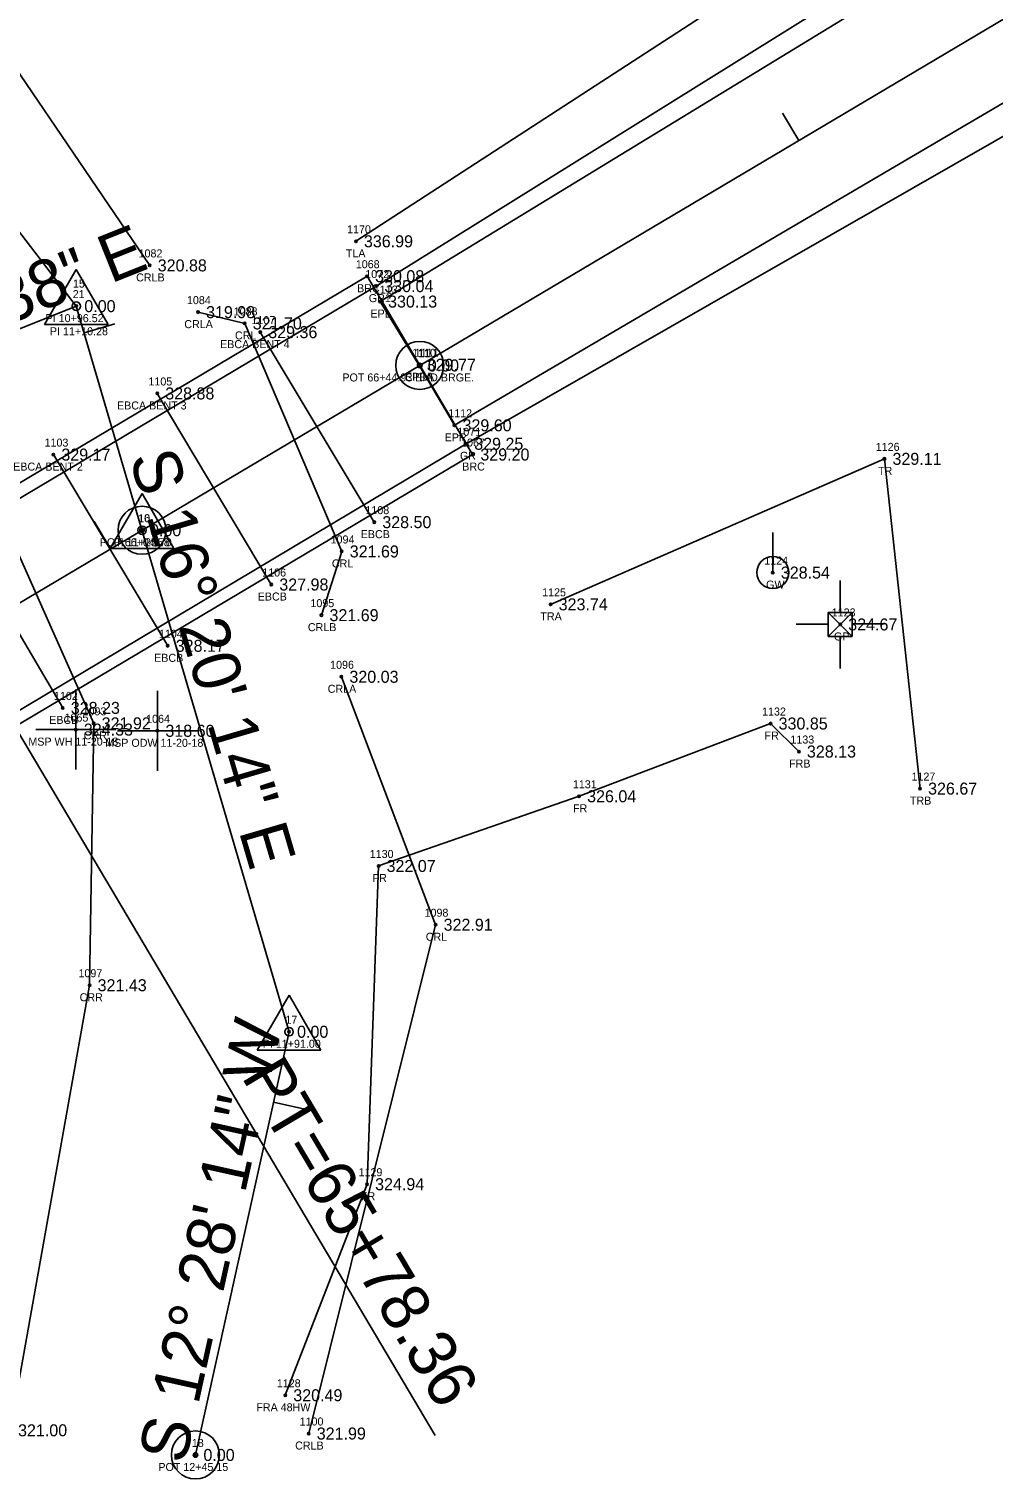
# Model space of a CAD drawing. Extents: x 2231119 to 2232595, y 1035731 to 1037094.
# Drawn here: x 2231557.4 to 2231678, y 1036323.7 to 1036504.9 of the extents above; entities that cross this region are included whole.
import ezdxf

# ---------------------------------------------------------------- set-up
doc = ezdxf.new("R2010")
doc.units = 0
for name, color, linetype in [('RD_EX_Bridge', 7, 'Continuous'), ('RD_EX_Bridge_txCode', 7, 'Continuous'), ('RD_EX_Fence_Other', 7, 'Continuous'), ('RD_EX_Fence_Other_txCode', 7, 'Continuous'), ('RD_EX_GuardRail', 7, 'Continuous'), ('RD_EX_GuardRail_txCode', 7, 'Continuous'), ('RD_EX_H2O', 7, 'Continuous'), ('RD_EX_H2O_txCode', 7, 'Continuous'), ('RD_EX_Road', 7, 'Continuous'), ('RD_EX_Road_txCode', 7, 'Continuous'), ('RD_EX_TX_Bridge_ELEV', 7, 'Continuous'), ('RD_EX_TX_Fence_Other_ELEV', 7, 'Continuous'), ('RD_EX_TX_GuardRail_ELEV', 7, 'Continuous'), ('RD_EX_TX_H2O_ELEV', 7, 'Continuous'), ('RD_EX_TX_Misc_ELEV', 7, 'Continuous'), ('RD_EX_TX_Road_ELEV', 7, 'Continuous'), ('RD_EX_TX_UT_ELEV', 7, 'Continuous'), ('RD_EX_TX_VEG_ELEV', 7, 'Continuous'), ('RD_EX_UT', 7, 'Continuous'), ('RD_EX_UT_txCode', 7, 'Continuous'), ('RD_EX_VEG', 7, 'Continuous'), ('RD_EX_VEG_txCode', 7, 'Continuous'), ('RD_HC_Cl', 7, 'Continuous'), ('RD_HC_Data', 7, 'Continuous'), ('RD_HC_Data_Tic', 7, 'Continuous'), ('RD_HC_Survey_ELEV', 7, 'Continuous'), ('RD_HC_txCode', 7, 'Continuous'), ('RD_SMD_Locator', 7, 'Continuous')]:
    doc.layers.add(name, color=color, linetype=linetype)

msp = doc.modelspace()

# ---------------------------------------------------------------- linework, layer by layer
at = {"layer": 'RD_EX_Bridge'}
for p, q in [((2231586.3, 1036467), (2231600.55, 1036443.26)), ((2231573.43, 1036459.34), (2231587.68, 1036435.47)), ((2231560.45, 1036451.7), (2231574.74, 1036427.81)), ((2231547.53, 1036444.05), (2231561.63, 1036420.05))]:
    msp.add_line(p, q, dxfattribs=at)
msp.add_lwpolyline([(2231548.42, 1036413.44), (2231612.8, 1036451.71), (2231599.65, 1036473.99), (2231535.22, 1036435.67), (2231548.41, 1036413.44)], dxfattribs=at)
at = {"layer": 'RD_EX_Fence_Other'}
msp.add_lwpolyline([(2231589.43, 1036334.17), (2231599.65, 1036360.54), (2231601.08, 1036400.3), (2231626.14, 1036409.01), (2231650.06, 1036418.1), (2231653.6, 1036414.6)], dxfattribs=at)
at = {"layer": 'RD_EX_GuardRail'}
for points in [[(2231465.75, 1036387.92), (2231495.75, 1036408.95), (2231535.82, 1036434.11), (2231600.8, 1036472.75), (2231670.25, 1036516.04)], [(2231470.54, 1036358.21), (2231510.97, 1036390.4), (2231547.27, 1036414.45), (2231612.03, 1036453.05), (2231683.18, 1036493.79)]]:
    msp.add_lwpolyline(points, dxfattribs=at)
at = {"layer": 'RD_EX_H2O'}
for p, q in [((2231563.26, 1036412.34), (2231563.26, 1036422.34)), ((2231573.45, 1036412.19), (2231573.45, 1036422.19)), ((2231558.26, 1036417.34), (2231568.26, 1036417.34)), ((2231568.45, 1036417.19), (2231578.45, 1036417.19))]:
    msp.add_line(p, q, dxfattribs=at)
for points in [[(2231513.64, 1036552.7), (2231545.27, 1036515.4), (2231572.49, 1036475.34)], [(2231578.53, 1036469.5), (2231584.36, 1036468.09), (2231596.48, 1036439.6), (2231593.95, 1036431.64)], [(2231550.29, 1036452.23), (2231565.49, 1036418.12), (2231564.98, 1036385.4), (2231555.04, 1036329.79)], [(2231596.44, 1036423.94), (2231608.21, 1036392.96), (2231592.36, 1036329.39)]]:
    msp.add_lwpolyline(points, dxfattribs=at)
for centre in [(2231563.26, 1036417.34), (2231573.45, 1036417.19)]:
    msp.add_circle(centre, 0.15, dxfattribs=at)
at = {"layer": 'RD_EX_Road'}
for points in [[(2231606.1, 1036462.92), (2231601.27, 1036470.82), (2231681.58, 1036519.84), (2231764.99, 1036568.78), (2231851.5, 1036619.95), (2231935.62, 1036669.65), (2232021.78, 1036720.22), (2232106.75, 1036770.57), (2232190.54, 1036819.2), (2232275.92, 1036870.27)], [(2231606.1, 1036462.92), (2231610.57, 1036455.36), (2231692.09, 1036503.24), (2231706.07, 1036512.59), (2231777.1, 1036553.27), (2231861.39, 1036604.65), (2231946.39, 1036654.77), (2232031.07, 1036704.2), (2232117.06, 1036755.16), (2232199.91, 1036803.8), (2232286.7, 1036855.36)]]:
    msp.add_lwpolyline(points, dxfattribs=at)
at = {"layer": 'RD_EX_UT'}
for p, q in [((2231650.34, 1036436.96), (2231650.34, 1036441.96)), ((2231658.76, 1036431.98), (2231658.76, 1036435.98)), ((2231660.26, 1036431.98), (2231657.26, 1036428.98)), ((2231657.26, 1036431.98), (2231660.26, 1036428.98)), ((2231660.26, 1036431.98), (2231657.26, 1036431.98)), ((2231657.26, 1036431.98), (2231657.26, 1036428.98)), ((2231660.26, 1036428.98), (2231660.26, 1036431.98)), ((2231657.24, 1036430.52), (2231653.24, 1036430.52)), ((2231660.28, 1036430.54), (2231664.29, 1036430.54)), ((2231657.26, 1036428.98), (2231660.26, 1036428.98)), ((2231658.76, 1036428.98), (2231658.76, 1036424.98))]:
    msp.add_line(p, q, dxfattribs=at)
msp.add_circle((2231650.34, 1036436.96), 2, dxfattribs=at)
at = {"layer": 'RD_EX_VEG'}
for points in [[(2231598.25, 1036478.35), (2231674.54, 1036527.95), (2231759.25, 1036584.63), (2231839.99, 1036637.88), (2231924.53, 1036692.24), (2232004.98, 1036742.14), (2232090.99, 1036793.16), (2232172.16, 1036843), (2232262.27, 1036890.61)], [(2231622.58, 1036432.99), (2231664.29, 1036451.17), (2231668.74, 1036409.97)]]:
    msp.add_lwpolyline(points, dxfattribs=at)
at = {"layer": 'RD_HC_Cl'}
for p, q in [((2231548.98, 1036428.87), (2232281.06, 1036863.23)), ((2231504.54, 1036546.81), (2231563.32, 1036470.25)), ((2231533.44, 1036458.33), (2231563.32, 1036470.25)), ((2231563.32, 1036470.25), (2231589.9, 1036379.59)), ((2231589.9, 1036379.59), (2231578.2, 1036326.71))]:
    msp.add_line(p, q, dxfattribs=at)
at = {"layer": 'RD_HC_Data'}
for p, q in [((2231559.35, 1036467.96), (2231563.32, 1036474.84)), ((2231559.35, 1036467.96), (2231563.32, 1036474.84)), ((2231563.32, 1036474.84), (2231567.29, 1036467.96)), ((2231563.32, 1036474.84), (2231567.29, 1036467.96)), ((2231559.35, 1036467.96), (2231567.29, 1036467.96)), ((2231559.35, 1036467.96), (2231567.29, 1036467.96)), ((2231567.56, 1036439.96), (2231571.53, 1036446.84)), ((2231571.53, 1036446.84), (2231575.5, 1036439.96)), ((2231567.56, 1036439.96), (2231575.5, 1036439.96)), ((2231548.98, 1036428.87), (2231608.15, 1036329.15)), ((2231585.93, 1036377.3), (2231589.9, 1036384.17)), ((2231589.9, 1036384.17), (2231593.87, 1036377.3)), ((2231585.93, 1036377.3), (2231593.87, 1036377.3))]:
    msp.add_line(p, q, dxfattribs=at)
for centre, radius in [((2231563.32, 1036470.25), 0.529), ((2231563.32, 1036470.25), 0.529), ((2231606.23, 1036462.84), 3), ((2231606.23, 1036462.84), 0.282), ((2231571.53, 1036442.25), 3), ((2231571.53, 1036442.25), 0.529), ((2231571.53, 1036442.25), 0.282), ((2231589.9, 1036379.59), 0.529), ((2231578.2, 1036326.71), 3), ((2231578.2, 1036326.71), 0.282)]:
    msp.add_circle(centre, radius, dxfattribs=at)
at = {"layer": 'RD_HC_Data_Tic'}
for p, q in [((2231653.59, 1036490.94), (2231651.55, 1036494.38)), ((2231564.3, 1036466.91), (2231568.14, 1036468.04)), ((2231567.59, 1036439.91), (2231565.55, 1036443.35)), ((2231587.95, 1036370.8), (2231591.86, 1036369.93))]:
    msp.add_line(p, q, dxfattribs=at)
at = {"layer": 'RD_SMD_Locator'}
for centre in [(2231598.25, 1036478.35), (2231572.49, 1036475.34), (2231599.65, 1036473.99), (2231600.8, 1036472.75), (2231563.32, 1036470.25), (2231563.32, 1036470.25), (2231601.27, 1036470.82), (2231578.53, 1036469.5), (2231584.36, 1036468.09), (2231586.3, 1036467), (2231606.1, 1036462.92), (2231606.1, 1036462.92), (2231606.23, 1036462.84), (2231573.43, 1036459.34), (2231610.57, 1036455.36), (2231560.45, 1036451.7), (2231612.03, 1036453.05), (2231612.8, 1036451.71), (2231664.29, 1036451.17), (2231600.55, 1036443.26), (2231571.53, 1036442.25), (2231571.53, 1036442.25), (2231596.48, 1036439.6), (2231587.68, 1036435.47), (2231650.34, 1036436.96), (2231593.95, 1036431.64), (2231622.58, 1036432.99), (2231658.76, 1036430.48), (2231574.74, 1036427.81), (2231596.44, 1036423.94), (2231561.63, 1036420.05), (2231565.49, 1036418.12), (2231650.06, 1036418.1), (2231653.6, 1036414.6), (2231668.74, 1036409.97), (2231626.14, 1036409.01), (2231601.08, 1036400.3), (2231608.21, 1036392.96), (2231564.98, 1036385.4), (2231589.9, 1036379.59), (2231599.65, 1036360.54), (2231589.43, 1036334.17), (2231592.36, 1036329.39), (2231578.2, 1036326.71)]:
    msp.add_circle(centre, 0.15, dxfattribs=at)

# ---------------------------------------------------------------- texts
at = {"layer": 'RD_EX_Bridge_txCode'}
for s, p in [('1068', (2231598.24, 1036474.99)), ('BRC', (2231598.4, 1036471.99)), ('1107', (2231585.2, 1036468)), ('EBCA BENT 4', (2231581.28, 1036465)), ('1105', (2231572.33, 1036460.34)), ('EBCA BENT 3', (2231568.4, 1036457.34)), ('1103', (2231559.35, 1036452.7)), ('1067', (2231611.39, 1036452.71)), ('EBCA BENT 2', (2231555.43, 1036449.7)), ('BRC', (2231611.54, 1036449.71)), ('1108', (2231599.44, 1036444.26)), ('EBCB', (2231598.85, 1036441.26)), ('1106', (2231586.55, 1036436.47)), ('EBCB', (2231585.98, 1036433.47)), ('1104', (2231573.64, 1036428.81)), ('EBCB', (2231573.04, 1036425.81)), ('1102', (2231560.52, 1036421.05)), ('EBCB', (2231559.93, 1036418.05))]:
    msp.add_text(s, height=1, dxfattribs=at).set_placement(p)
at = {"layer": 'RD_EX_Fence_Other_txCode'}
for s, p in [('1132', (2231649, 1036419.1)), ('FR', (2231649.3, 1036416.1)), ('1133', (2231652.54, 1036415.6)), ('FRB', (2231652.37, 1036412.6)), ('1131', (2231625.36, 1036410.01)), ('FR', (2231625.38, 1036407.01)), ('1130', (2231599.98, 1036401.3)), ('FR', (2231600.33, 1036398.3)), ('1129', (2231598.58, 1036361.54)), ('FR', (2231598.89, 1036358.54)), ('1128', (2231588.37, 1036335.17)), ('FRA 48HW', (2231585.81, 1036332.17))]:
    msp.add_text(s, height=1, dxfattribs=at).set_placement(p)
at = {"layer": 'RD_EX_GuardRail_txCode'}
for s, p in [('1072', (2231599.42, 1036473.75)), ('GR1', (2231599.86, 1036470.75)), ('1071', (2231610.93, 1036454.05)), ('GR', (2231611.25, 1036451.05))]:
    msp.add_text(s, height=1, dxfattribs=at).set_placement(p)
at = {"layer": 'RD_EX_H2O_txCode'}
for s, p in [('1082', (2231571.1, 1036476.34)), ('CRLB', (2231570.79, 1036473.34)), ('1084', (2231577.14, 1036470.5)), ('1088', (2231582.98, 1036469.09)), ('CRLA', (2231576.81, 1036467.5)), ('CRL', (2231583.14, 1036466.09)), ('1094', (2231595.09, 1036440.6)), ('CRL', (2231595.25, 1036437.6)), ('1095', (2231592.57, 1036432.64)), ('CRLB', (2231592.25, 1036429.64)), ('1096', (2231595.03, 1036424.94)), ('CRLA', (2231594.73, 1036421.94)), ('1065', (2231561.85, 1036418.34)), ('1093', (2231564.1, 1036419.12)), ('1064', (2231572.04, 1036418.19)), ('MSP WH 11-20-18', (2231557.33, 1036415.34)), ('CRR', (2231564.24, 1036416.12)), ('MSP ODW 11-20-18', (2231566.93, 1036415.19)), ('1098', (2231606.83, 1036393.96)), ('CRL', (2231606.98, 1036390.96)), ('1097', (2231563.59, 1036386.4)), ('CRR', (2231563.73, 1036383.4)), ('1100', (2231591.22, 1036330.39)), ('CRLB', (2231590.66, 1036327.39))]:
    msp.add_text(s, height=1, dxfattribs=at).set_placement(p)
at = {"layer": 'RD_EX_Road_txCode'}
for s, p in [('1113', (2231600.49, 1036471.82)), ('EPL', (2231600.07, 1036468.82)), ('1110', (2231605.28, 1036463.92)), ('1111', (2231605.6, 1036463.92)), ('EPRA', (2231604.38, 1036460.92)), ('EPLA', (2231604.41, 1036460.92)), ('1112', (2231609.79, 1036456.36)), ('EPR', (2231609.34, 1036453.36))]:
    msp.add_text(s, height=1, dxfattribs=at).set_placement(p)
at = {"layer": 'RD_EX_TX_Bridge_ELEV'}
for s, p in [('330.08', (2231600.65, 1036473.24)), ('329.36', (2231587.3, 1036466.25)), ('328.88', (2231574.43, 1036458.59)), ('329.17', (2231561.45, 1036450.95)), ('329.20', (2231613.8, 1036450.96)), ('328.50', (2231601.55, 1036442.51)), ('327.98', (2231588.68, 1036434.72)), ('328.17', (2231575.74, 1036427.06)), ('328.23', (2231562.63, 1036419.3))]:
    msp.add_text(s, height=1.5, dxfattribs=at).set_placement(p)
at = {"layer": 'RD_EX_TX_Fence_Other_ELEV'}
for s, p in [('330.85', (2231651.06, 1036417.35)), ('328.13', (2231654.6, 1036413.85)), ('326.04', (2231627.14, 1036408.26)), ('322.07', (2231602.08, 1036399.55)), ('324.94', (2231600.65, 1036359.79)), ('320.49', (2231590.43, 1036333.42))]:
    msp.add_text(s, height=1.5, dxfattribs=at).set_placement(p)
at = {"layer": 'RD_EX_TX_GuardRail_ELEV'}
for s, p in [('330.04', (2231601.8, 1036472)), ('329.25', (2231613.03, 1036452.3))]:
    msp.add_text(s, height=1.5, dxfattribs=at).set_placement(p)
at = {"layer": 'RD_EX_TX_H2O_ELEV'}
for s, p in [('320.88', (2231573.49, 1036474.59)), ('319.98', (2231579.53, 1036468.75)), ('321.70', (2231585.36, 1036467.34)), ('321.69', (2231597.48, 1036438.85)), ('321.69', (2231594.95, 1036430.89)), ('320.03', (2231597.44, 1036423.19)), ('321.92', (2231566.49, 1036417.37)), ('322.91', (2231609.21, 1036392.21)), ('321.43', (2231565.98, 1036384.65)), ('321.00', (2231556.04, 1036329.04)), ('321.99', (2231593.36, 1036328.64))]:
    msp.add_text(s, height=1.5, dxfattribs=at).set_placement(p)
at = {"layer": 'RD_EX_TX_Misc_ELEV'}
for s, p in [('324.33', (2231564.26, 1036416.59)), ('318.60', (2231574.45, 1036416.44))]:
    msp.add_text(s, height=1.5, dxfattribs=at).set_placement(p)
at = {"layer": 'RD_EX_TX_Road_ELEV'}
for s, p in [('330.13', (2231602.27, 1036470.07)), ('329.77', (2231607.1, 1036462.17)), ('329.77', (2231607.1, 1036462.17)), ('329.60', (2231611.57, 1036454.61))]:
    msp.add_text(s, height=1.5, dxfattribs=at).set_placement(p)
at = {"layer": 'RD_EX_TX_UT_ELEV'}
for s, p in [('328.54', (2231651.34, 1036436.21)), ('324.67', (2231659.76, 1036429.73))]:
    msp.add_text(s, height=1.5, dxfattribs=at).set_placement(p)
at = {"layer": 'RD_EX_TX_VEG_ELEV'}
for s, p in [('336.99', (2231599.25, 1036477.6)), ('329.11', (2231665.29, 1036450.42)), ('323.74', (2231623.58, 1036432.24)), ('326.67', (2231669.74, 1036409.22))]:
    msp.add_text(s, height=1.5, dxfattribs=at).set_placement(p)
at = {"layer": 'RD_EX_UT_txCode'}
for s, p in [('1124', (2231649.28, 1036437.96)), ('GW', (2231649.5, 1036434.96)), ('1123', (2231657.7, 1036431.48)), ('GP', (2231657.98, 1036428.48))]:
    msp.add_text(s, height=1, dxfattribs=at).set_placement(p)
at = {"layer": 'RD_EX_VEG_txCode'}
for s, p in [('1170', (2231597.15, 1036479.35)), ('TLA', (2231596.99, 1036476.35)), ('1126', (2231663.2, 1036452.17)), ('TR', (2231663.49, 1036449.17)), ('1125', (2231621.52, 1036433.99)), ('TRA', (2231621.3, 1036430.99)), ('1127', (2231667.67, 1036410.97)), ('TRB', (2231667.47, 1036407.97))]:
    msp.add_text(s, height=1, dxfattribs=at).set_placement(p)
at = {"layer": 'RD_HC_Data'}
for s, rotation, p in [('N 68%%d 14\' 38" E', 21.756, (2231522.02, 1036454.85)), ('S 16%%d 20\' 14" E', 286.3373, (2231569.91, 1036451.35)), ('S 12%%d 28\' 14" W', 77.5295, (2231576.9, 1036325.45)), ('PT=65+78.36', 300.682, (2231583.87, 1036373.99))]:
    msp.add_text(s, height=6, rotation=rotation, dxfattribs=at).set_placement(p)
at = {"layer": 'RD_HC_Survey_ELEV'}
for p in [(2231564.32, 1036469.5), (2231564.32, 1036469.5), (2231607.23, 1036462.09), (2231572.53, 1036441.5), (2231572.53, 1036441.5), (2231590.9, 1036378.84), (2231579.2, 1036325.96)]:
    msp.add_text('0.00', height=1.5, dxfattribs=at).set_placement(p)
at = {"layer": 'RD_HC_txCode'}
for s, p in [('15', (2231562.9, 1036472.57)), ('21', (2231562.87, 1036471.25)), ('PI 10+96.52', (2231559.48, 1036468.25)), ('PI 11+10.28', (2231560.02, 1036466.61)), ('11', (2231606.06, 1036463.84)), ('POT 66+44.93 END BRGE.', (2231596.56, 1036460.84)), ('10', (2231571.04, 1036443.25)), ('16', (2231571.06, 1036443.25)), ('POT 66+04.58', (2231566.25, 1036440.25)), ('PI 11+25.70', (2231567.99, 1036440.25)), ('17', (2231589.45, 1036380.59)), ('PI 11+91.00', (2231586.61, 1036377.59)), ('18', (2231577.75, 1036327.71)), ('POT 12+45.15', (2231573.57, 1036324.71))]:
    msp.add_text(s, height=1, dxfattribs=at).set_placement(p)

doc.saveas('drawing.dxf')
